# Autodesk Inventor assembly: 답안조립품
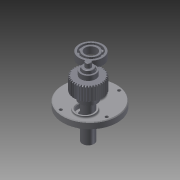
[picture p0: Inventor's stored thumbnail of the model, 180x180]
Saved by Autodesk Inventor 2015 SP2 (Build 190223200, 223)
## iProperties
Created: 2015-06
Part Number: 답안조립품
Document SubType Name: Assembly
Designer: AMC
Author: AMC
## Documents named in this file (8)
- C:\Users\AMC\Desktop\450620V1003\답안조립품.iam
- C:\Users\AMC\Desktop\450620V1003\본체.ipt
- C:\Users\AMC\Desktop\450620V1003\베어링 608.ipt
- 베어링 608.ipt
- C:\Users\AMC\Desktop\450620V1003\베어링 6003.ipt
- 베어링 6003.ipt
- C:\Users\AMC\Desktop\450620V1003\커버.ipt
- C:\Users\AMC\Desktop\450620V1003\서브축.ipt
